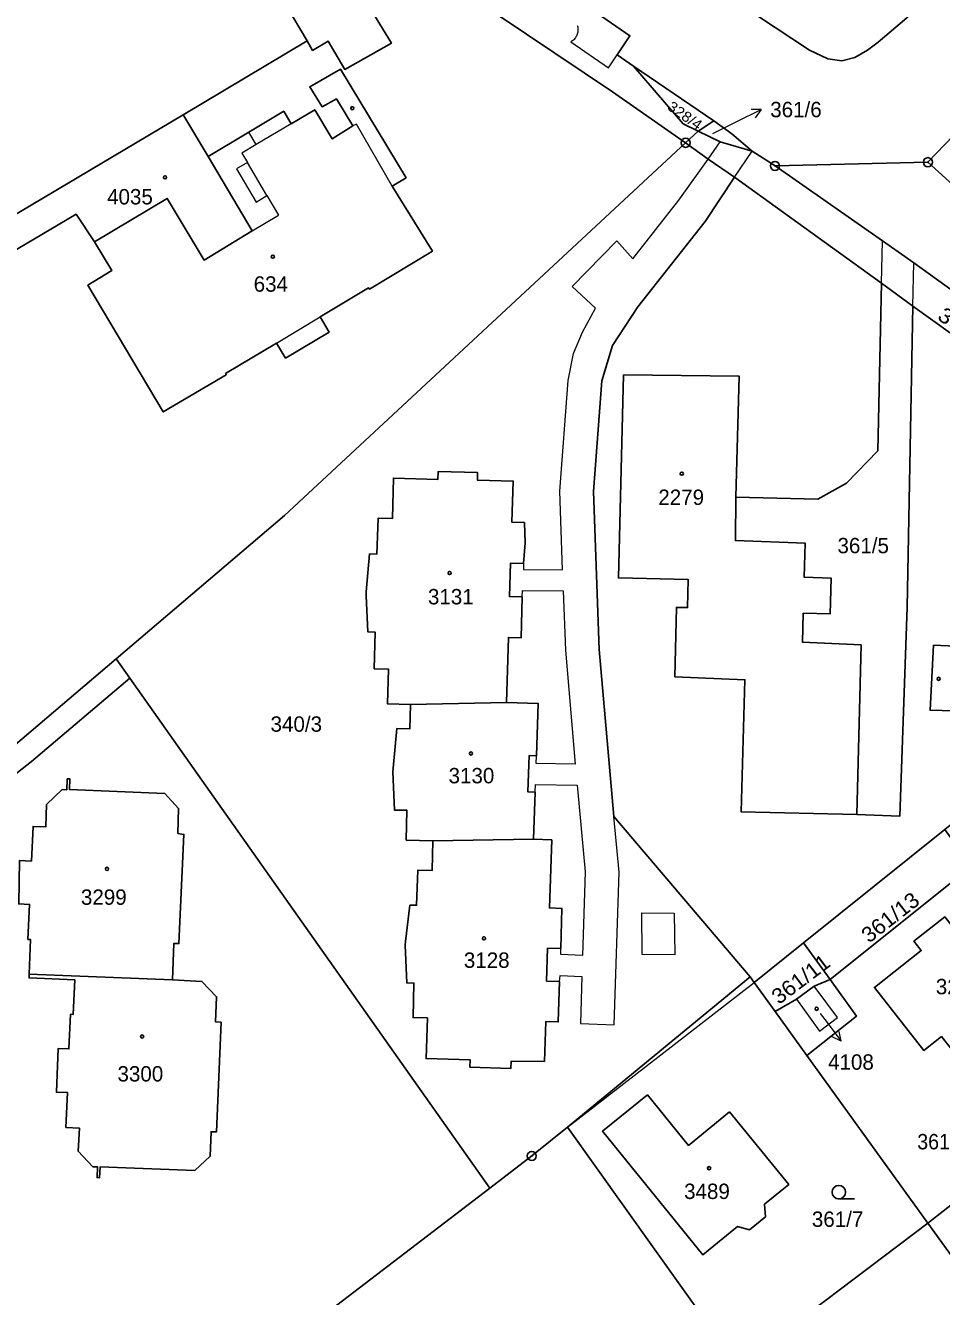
# Model space of a CAD drawing. Extents: x -679733 to -673243, y -1075091 to -1066557.
# Drawn here: x -675742.5 to -675641.2, y -1072480.8 to -1072340.3 of the extents above; entities that cross this region are included whole.
import ezdxf
from ezdxf.enums import TextEntityAlignment as Align

# ---------------------------------------------------------------- set-up
doc = ezdxf.new("R2010")
doc.units = 0
doc.header["$LTSCALE"] = 0.68
for name, color, linetype, lineweight in [('1', 7, 'Continuous', 25), ('3', 7, 'Continuous', 25), ('4', 7, 'Continuous', 13), ('5', 7, 'Continuous', 25), ('7', 7, 'Continuous', 13), ('8', 7, 'Continuous', 25)]:
    doc.layers.add(name, color=color, linetype=linetype, lineweight=lineweight)
doc.layers.add('2', color=7, linetype='Continuous')

msp = doc.modelspace()

# ---------------------------------------------------------------- linework, layer by layer
at = {"layer": '1'}
for p, q in [((-675635.81, -1072348.19), (-675642.72, -1072355.42)), ((-675722.26, -1072354.81), (-675717.38, -1072363.02)), ((-675659.61, -1072355.83), (-675662.15, -1072354.2)), ((-675659.61, -1072355.83), (-675642.72, -1072355.42)), ((-675642.72, -1072355.42), (-675630.17, -1072366.89)), ((-675647.85, -1072368.81), (-675644.37, -1072371.32)), ((-675604.49, -1072400.1), (-675644.37, -1072371.32)), ((-675699.9, -1072415.37), (-675689.29, -1072415.14)), ((-675686.31, -1072430.24), (-675697.42, -1072430.44)), ((-675637.91, -1072433.26), (-675653.53, -1072445.76)), ((-675742.04, -1072445.16), (-675726.21, -1072445.79))]:
    msp.add_line(p, q, dxfattribs=at)
for points in [[(-675675.24, -1072344.8), (-675677.06, -1072343.56), (-675675.65, -1072341.45), (-675809.62, -1072248.86), (-675810.47, -1072252.39), (-675814.41, -1072249.48), (-675828.02, -1072240.66), (-675831.19, -1072238.38), (-675834.37, -1072240.28), (-675799.8, -1072264.22)], [(-675669.24, -1072334.12), (-675655.8, -1072343.03), (-675653.77, -1072343.98), (-675652.23, -1072344.22), (-675650.78, -1072343.84), (-675649.38, -1072343.04), (-675648.22, -1072342.16), (-675645.05, -1072339.48), (-675631.58, -1072324.1), (-675631.9, -1072323.72)], [(-675709.33, -1072326.32), (-675677.59, -1072347.66), (-675669.49, -1072353.28), (-675668.11, -1072352)], [(-675711.33, -1072342.02), (-675713.64, -1072338.09), (-675711.95, -1072337.02), (-675713.87, -1072333.86), (-675708.89, -1072330.86)], [(-675711.33, -1072342.02), (-675710.72, -1072343.06), (-675708.98, -1072342.06), (-675707.16, -1072345.17), (-675702.01, -1072342.25), (-675703.98, -1072339.04), (-675702.29, -1072337.99), (-675705.26, -1072333.08), (-675706.92, -1072334.09), (-675708.89, -1072330.86)], [(-675764.69, -1072354.25), (-675762.97, -1072353.34), (-675761.31, -1072356.47), (-675762.83, -1072357.28), (-675755.91, -1072368.55), (-675725.02, -1072350.17), (-675711.33, -1072342.02)], [(-675734.83, -1072364.22), (-675732.9, -1072367.39), (-675735.56, -1072369.02), (-675727.22, -1072383.03), (-675720.26, -1072378.91), (-675720.34, -1072378.78), (-675714.71, -1072375.41), (-675713.7, -1072377.08), (-675708.87, -1072374.2), (-675709.88, -1072372.52), (-675704.52, -1072369.32), (-675704.44, -1072369.45), (-675697.48, -1072365.26), (-675701.91, -1072358.08), (-675700.39, -1072357.15), (-675707.64, -1072345.13), (-675711.04, -1072347.09), (-675709.67, -1072349.3), (-675708.09, -1072348.42), (-675706.27, -1072351.42), (-675708.54, -1072352.84), (-675710.47, -1072349.63), (-675713.08, -1072351.18), (-675713.9, -1072349.8), (-675717.75, -1072352.09), (-675722.26, -1072354.81)], [(-675668.11, -1072352), (-675669.76, -1072351.2), (-675675.24, -1072344.8)], [(-675668.11, -1072352), (-675666.37, -1072350.85), (-675675.24, -1072344.8)], [(-675725.02, -1072350.17), (-675724.95, -1072350.29), (-675722.26, -1072354.81)], [(-675662.15, -1072354.2), (-675664.37, -1072352.28), (-675666.37, -1072350.85)], [(-675662.15, -1072354.2), (-675665.66, -1072353.18), (-675668.11, -1072352)], [(-675669.49, -1072353.28), (-675713.82, -1072394.47), (-675732.43, -1072410.33)], [(-675664.09, -1072357.09), (-675667, -1072355.07), (-675669.49, -1072353.28)], [(-675604.49, -1072400.1), (-675629.64, -1072377.07), (-675644.28, -1072366.54), (-675647.74, -1072364.12), (-675659.61, -1072355.83)], [(-675662.37, -1072445.46), (-675677.41, -1072427.73), (-675679.06, -1072409.27), (-675679.67, -1072391.84), (-675678.76, -1072379.59), (-675677.57, -1072375.68), (-675674.76, -1072371.4), (-675667.34, -1072361.96), (-675664.09, -1072357.09)], [(-675663.96, -1072392.44), (-675654.87, -1072392.66), (-675651.73, -1072390.92), (-675648.26, -1072387.33), (-675647.85, -1072368.81), (-675664.09, -1072357.09)], [(-675717.38, -1072363.02), (-675722.71, -1072366.24), (-675726.78, -1072359.42), (-675734.83, -1072364.22)], [(-675734.83, -1072364.22), (-675736.86, -1072361.17), (-675772.1, -1072382.03)], [(-675644.37, -1072371.32), (-675645.02, -1072404.62), (-675645.81, -1072427.7), (-675650.57, -1072427.52)], [(-675663.96, -1072392.44), (-675663.57, -1072379.09), (-675676.35, -1072378.94), (-675676.91, -1072401.38), (-675669.21, -1072401.56), (-675669.28, -1072404.66), (-675670.5, -1072404.63), (-675670.68, -1072412.3), (-675662.93, -1072412.63), (-675663.35, -1072427.25), (-675650.57, -1072427.52)], [(-675689.29, -1072415.14), (-675689.08, -1072407.96), (-675687.68, -1072408.01), (-675687.56, -1072403.48), (-675688.96, -1072403.43), (-675688.85, -1072399.75), (-675687.4, -1072399.79), (-675687.22, -1072397.51), (-675687.3, -1072395.25), (-675688.68, -1072395.23), (-675688.55, -1072390.67), (-675692.51, -1072390.57), (-675692.48, -1072389.73), (-675696.84, -1072389.63), (-675696.86, -1072390.48), (-675701.79, -1072390.34), (-675701.89, -1072394.82), (-675703.48, -1072394.78), (-675703.61, -1072398.74), (-675704.41, -1072398.72), (-675704.79, -1072402.93), (-675704.81, -1072403.35), (-675704.6, -1072407.34), (-675703.81, -1072407.36), (-675703.91, -1072411.41), (-675702.31, -1072411.47), (-675702.44, -1072415.28), (-675699.9, -1072415.37)], [(-675650.57, -1072427.52), (-675650.1, -1072408.78), (-675656.59, -1072408.46), (-675656.5, -1072405.28), (-675653.52, -1072405.36), (-675653.41, -1072401.39), (-675656.39, -1072401.31), (-675656.29, -1072397.53), (-675663.98, -1072397.24), (-675663.96, -1072392.44)], [(-675789.23, -1072455.87), (-675780.02, -1072449.59), (-675762.22, -1072437.39), (-675751.96, -1072429.64), (-675741.8, -1072421.67), (-675730.93, -1072412.45), (-675732.43, -1072410.33)], [(-675732.43, -1072410.33), (-675748.06, -1072423.6), (-675767.77, -1072438.97), (-675788.79, -1072452.73)], [(-675708.65, -1072482.25), (-675691.14, -1072468.83), (-675730.93, -1072412.45)], [(-675662.37, -1072445.46), (-675661.92, -1072446.08), (-675656.45, -1072441.72), (-675640.84, -1072429.2), (-675620.86, -1072413.2)], [(-675697.42, -1072430.44), (-675700.36, -1072430.36), (-675700.3, -1072427.06), (-675701.66, -1072427.05), (-675701.84, -1072422.82), (-675701.83, -1072422.4), (-675701.39, -1072418.02), (-675699.98, -1072418.06), (-675699.9, -1072415.37)], [(-675689.29, -1072415.14), (-675685.8, -1072415.25), (-675685.98, -1072421.03), (-675686.78, -1072421), (-675686.92, -1072425.03), (-675686.13, -1072425.06), (-675686.31, -1072430.24)], [(-675742.04, -1072445.16), (-675741.88, -1072441.35), (-675742.18, -1072441.34), (-675742, -1072437.47), (-675743.2, -1072437.42), (-675743.09, -1072432.61), (-675741.79, -1072432.68), (-675741.61, -1072428.84), (-675740.18, -1072428.89), (-675740.11, -1072426.41), (-675738.38, -1072424.77), (-675737.88, -1072424.79), (-675737.83, -1072423.59), (-675737.53, -1072423.6), (-675737.57, -1072424.78), (-675727.05, -1072425.19), (-675725.53, -1072426.86), (-675725.6, -1072429.62), (-675724.94, -1072429.73), (-675725.49, -1072441.79), (-675726.05, -1072441.77), (-675726.21, -1072445.79)], [(-675642.71, -1072472.71), (-675621.45, -1072456.06), (-675637.91, -1072433.26), (-675640.84, -1072429.2)], [(-675686.31, -1072430.24), (-675684.28, -1072430.34), (-675684.55, -1072437.86), (-675683.17, -1072437.91), (-675683.3, -1072442.35), (-675684.74, -1072442.3), (-675684.86, -1072445.94), (-675683.43, -1072445.99), (-675683.56, -1072450.46), (-675684.95, -1072450.41), (-675685.09, -1072454.82), (-675688.77, -1072454.78), (-675688.8, -1072455.59), (-675693.34, -1072455.45), (-675693.31, -1072454.66), (-675698.18, -1072454.5), (-675698.03, -1072450.02), (-675699.62, -1072449.97), (-675699.52, -1072446.17), (-675700.32, -1072446.14), (-675700.48, -1072441.98), (-675700.46, -1072441.55), (-675699.97, -1072437.55), (-675699.22, -1072437.56), (-675699.07, -1072433.67), (-675697.5, -1072433.71), (-675697.42, -1072430.44)], [(-675655.29, -1072446.49), (-675653.53, -1072445.76), (-675656.45, -1072441.72)], [(-675726.21, -1072445.79), (-675722.95, -1072445.97), (-675721.32, -1072447.67), (-675721.46, -1072450.43), (-675720.83, -1072450.5), (-675721.33, -1072462.6), (-675721.94, -1072462.59), (-675722.03, -1072465.29), (-675723.73, -1072466.87), (-675734.2, -1072466.48), (-675734.25, -1072467.68), (-675734.53, -1072467.67), (-675734.48, -1072466.48), (-675734.99, -1072466.46), (-675736.62, -1072464.75), (-675736.47, -1072462.21), (-675737.97, -1072462.12), (-675737.82, -1072458.27), (-675739.02, -1072458.22), (-675738.84, -1072453.4), (-675737.64, -1072453.44), (-675737.49, -1072449.61), (-675737.17, -1072449.62), (-675737.01, -1072445.81), (-675742.05, -1072445.6), (-675742.04, -1072445.16)], [(-675691.14, -1072468.83), (-675686.49, -1072465.27), (-675682.54, -1072462.08), (-675662.37, -1072445.46)], [(-675656.08, -1072454.18), (-675659.59, -1072449.31), (-675661.92, -1072446.08)], [(-675659.59, -1072449.31), (-675657.24, -1072447.94), (-675655.29, -1072446.49)], [(-675653.53, -1072445.76), (-675650.6, -1072449.81), (-675656.08, -1072454.18)], [(-675663.69, -1072488.56), (-675642.71, -1072472.71), (-675656.08, -1072454.18)], [(-675689.59, -1072508.13), (-675663.69, -1072488.56), (-675682.54, -1072462.08)], [(-675656.72, -1072498.35), (-675635.77, -1072482.33), (-675642.71, -1072472.71)]]:
    msp.add_lwpolyline(points, dxfattribs=at)
for points in [[(-675642.11, -1072408.81), (-675642.47, -1072416), (-675638.46, -1072416.12), (-675638.09, -1072409.01)], [(-675641.2, -1072452.08), (-675638.72, -1072455.25), (-675636.72, -1072455.48), (-675635.09, -1072454.17), (-675634.98, -1072452.74), (-675630.2, -1072448.99), (-675638.34, -1072438.59), (-675640, -1072439.9), (-675640.83, -1072438.84), (-675644.26, -1072441.54), (-675643.45, -1072442.57), (-675648.62, -1072446.64), (-675643.16, -1072453.61)], [(-675664.63, -1072460.4), (-675658.1, -1072468.42), (-675660.76, -1072470.61), (-675660.67, -1072472.01), (-675662.43, -1072473.45), (-675663.77, -1072473.07), (-675667.59, -1072476.2), (-675678.66, -1072462.54), (-675673.71, -1072458.52), (-675669.17, -1072464.1)]]:
    msp.add_lwpolyline(points, close=True, dxfattribs=at)
at = {"layer": '3'}
msp.add_line((-675652.563, -1072470.02), (-675650.813, -1072470.02), dxfattribs=at)
msp.add_circle((-675652.5629, -1072469.2698), 0.75, dxfattribs=at)
at = {"layer": '4'}
for p, q in [((-675682.16, -1072342.12), (-675678.01, -1072344.99)), ((-675678.01, -1072344.99), (-675677.06, -1072343.56)), ((-675713.08, -1072351.18), (-675716.94, -1072353.47)), ((-675716.94, -1072353.47), (-675717.75, -1072352.09)), ((-675705.88, -1072351.22), (-675706.27, -1072351.42)), ((-675701.91, -1072358.08), (-675705.88, -1072351.22)), ((-675716.94, -1072353.47), (-675718.53, -1072354.42)), ((-675667, -1072355.07), (-675665.66, -1072353.18)), ((-675718.53, -1072354.42), (-675717.92, -1072355.46)), ((-675670.24, -1072359.62), (-675667, -1072355.07)), ((-675664.09, -1072357.09), (-675662.15, -1072354.2)), ((-675717.92, -1072355.46), (-675719.13, -1072356.17)), ((-675719.13, -1072356.17), (-675716.97, -1072359.83)), ((-675715.77, -1072359.11), (-675717.92, -1072355.46)), ((-675716.97, -1072359.83), (-675715.77, -1072359.11)), ((-675715.77, -1072359.11), (-675714.49, -1072361.28)), ((-675675.31, -1072366.12), (-675670.24, -1072359.62)), ((-675717.38, -1072363.02), (-675714.49, -1072361.28)), ((-675682.04, -1072369.18), (-675677.1, -1072364.11)), ((-675677.1, -1072364.11), (-675675.31, -1072366.12)), ((-675647.85, -1072368.81), (-675647.74, -1072364.12)), ((-675644.37, -1072371.32), (-675644.28, -1072366.54)), ((-675679.44, -1072371.56), (-675682.04, -1072369.18)), ((-675680.87, -1072374.2), (-675679.44, -1072371.56)), ((-675714.71, -1072375.41), (-675709.88, -1072372.52)), ((-675681.87, -1072376.57), (-675680.87, -1072374.2)), ((-675682.46, -1072379.57), (-675681.87, -1072376.57)), ((-675683.4, -1072391.77), (-675682.46, -1072379.57)), ((-675683.08, -1072400.5), (-675683.4, -1072391.77)), ((-675687.4, -1072399.79), (-675687.41, -1072400.43)), ((-675687.41, -1072400.43), (-675683.08, -1072400.5)), ((-675687.56, -1072403.48), (-675687.52, -1072402.76)), ((-675687.52, -1072402.76), (-675683.03, -1072402.79)), ((-675683.03, -1072402.79), (-675682.78, -1072409.38)), ((-675682.78, -1072409.38), (-675681.69, -1072421.97)), ((-675686.01, -1072421.9), (-675685.98, -1072421.03)), ((-675681.69, -1072421.97), (-675686.01, -1072421.9)), ((-675686.13, -1072425.06), (-675686.1, -1072424.21)), ((-675686.1, -1072424.21), (-675681.47, -1072424.28)), ((-675681.47, -1072424.28), (-675680.59, -1072433.85)), ((-675676.85, -1072433.89), (-675677.41, -1072427.73)), ((-675680.59, -1072433.85), (-675680.88, -1072443.11)), ((-675677.4, -1072450.77), (-675676.85, -1072433.89)), ((-675674.31, -1072443.02), (-675674.32, -1072438.39)), ((-675674.32, -1072438.39), (-675670.75, -1072438.44)), ((-675670.75, -1072438.44), (-675670.7, -1072443.04)), ((-675683.29, -1072443.02), (-675683.3, -1072442.35)), ((-675680.88, -1072443.11), (-675683.29, -1072443.02)), ((-675670.7, -1072443.04), (-675674.31, -1072443.02)), ((-675683.43, -1072445.99), (-675683.36, -1072445.33)), ((-675683.36, -1072445.33), (-675680.95, -1072445.44)), ((-675682.54, -1072462.08), (-675661.92, -1072446.08)), ((-675680.95, -1072445.44), (-675681.1, -1072450.63)), ((-675681.1, -1072450.63), (-675677.4, -1072450.77))]:
    msp.add_line(p, q, dxfattribs=at)
for points in [[(-675681.473, -1072340.295), (-675681.442, -1072340.401), (-675681.42, -1072340.51), (-675681.404, -1072340.62), (-675681.397, -1072340.73), (-675681.398, -1072340.841), (-675681.406, -1072340.951), (-675681.422, -1072341.061), (-675681.446, -1072341.169), (-675681.478, -1072341.276), (-675681.517, -1072341.379), (-675681.563, -1072341.48), (-675681.617, -1072341.577), (-675681.677, -1072341.67), (-675681.743, -1072341.759), (-675681.816, -1072341.843), (-675681.894, -1072341.921), (-675681.978, -1072341.994), (-675682.067, -1072342.06), (-675682.16, -1072342.12)], [(-675657.24, -1072447.94), (-675654.68, -1072451.48), (-675652.71, -1072449.96), (-675655.29, -1072446.49)]]:
    msp.add_lwpolyline(points, dxfattribs=at)
at = {"layer": '5'}
for centre in [(-675706.3268, -1072349.4492), (-675727.0268, -1072357.0992), (-675715.1068, -1072365.8692), (-675669.9168, -1072389.8592), (-675695.5768, -1072400.8392), (-675641.5268, -1072412.5292), (-675693.2068, -1072420.7892), (-675733.4368, -1072433.5392), (-675691.7768, -1072441.2192), (-675655.0168, -1072448.9992), (-675729.5468, -1072452.0692), (-675666.8968, -1072466.6192)]:
    msp.add_circle(centre, 0.175, dxfattribs=at)
at = {"layer": '7'}
for p, q in [((-675661.133, -1072349.614), (-675662.252, -1072349.603)), ((-675652.304, -1072452.597), (-675652.507, -1072451.496))]:
    msp.add_line(p, q, dxfattribs=at)
for points in [[(-675666.5, -1072352.26), (-675663.83, -1072350.93), (-675661.133, -1072349.614), (-675661.813, -1072350.504)], [(-675654.62, -1072449.52), (-675654.11, -1072450.2), (-675652.304, -1072452.597), (-675653.307, -1072452.098)]]:
    msp.add_lwpolyline(points, dxfattribs=at)
at = {"layer": '8'}
for centre, radius in [((-675669.49, -1072353.2799), 0.5), ((-675669.49, -1072353.2799), 0.0303), ((-675659.61, -1072355.8299), 0.5), ((-675642.72, -1072355.4199), 0.5), ((-675642.72, -1072355.4199), 0.0303), ((-675659.61, -1072355.8299), 0.0303), ((-675686.49, -1072465.2699), 0.5), ((-675686.49, -1072465.2699), 0.0303)]:
    msp.add_circle(centre, radius, dxfattribs=at)

# ---------------------------------------------------------------- texts
at = {"layer": '2'}
for s, height, rotation, width, p in [('328/4', 1.14, 325, 1.1, (-675671.606, -1072349.526)), ('361/4', 1.7, 325, 1.1, (-675641.777, -1072372.716)), ('361/13', 1.7, 38, 1.05, (-675649.226, -1072441.809)), ('361/11', 1.7, 37, 1.05, (-675659.178, -1072448.598))]:
    msp.add_text(s, height=height, rotation=rotation, dxfattribs=dict(at, width=width)).set_placement(p)
for s, p in [('361/6', (-675660.14, -1072350.45)), ('634', (-675717.23, -1072369.739)), ('2279', (-675672.51, -1072393.31)), ('361/5', (-675652.71, -1072398.65)), ('3131', (-675697.97, -1072404.3)), ('340/3', (-675715.36, -1072418.38)), ('3130', (-675695.69, -1072424.08)), ('3299', (-675736.32, -1072437.509)), ('3128', (-675694, -1072444.479)), ('3205', (-675641.84, -1072447.4)), ('3300', (-675732.28, -1072457.04)), ('3489', (-675669.66, -1072470.029)), ('361/7', (-675655.54, -1072473.11))]:
    msp.add_text(s, height=1.7, dxfattribs=at).set_placement(p)
for s, p in [('4035', (-675730.9, -1072360.09)), ('4108', (-675651.22, -1072455.739))]:
    msp.add_text(s, height=1.7, dxfattribs=at).set_placement(p, align=Align.CENTER)
at = {"layer": '2', "width": 0.95}
msp.add_text('361/12', height=1.7, dxfattribs=at).set_placement((-675643.89, -1072464.54))

doc.saveas('drawing.dxf')
